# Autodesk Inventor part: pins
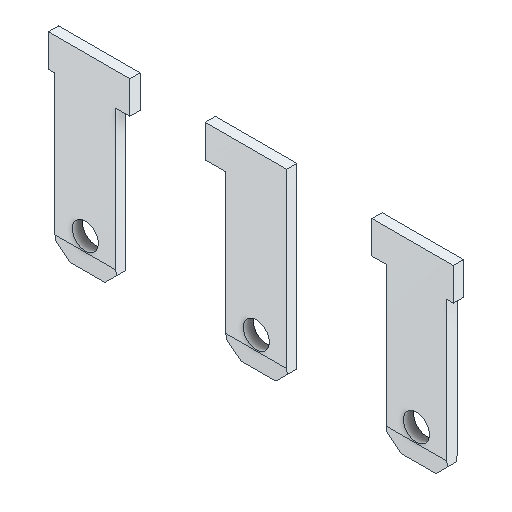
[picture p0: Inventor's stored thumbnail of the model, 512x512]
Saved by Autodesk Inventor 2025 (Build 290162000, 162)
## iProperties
Created: 2025-10
Part Number: pins
Material: Generico
Document SubType Name: Modeling
Designer: Ryzen5700u
Density: 1 g/cm^3
Appearance: Default
Author: Ryzen5700u
Revision Number: ANY
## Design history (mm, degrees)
feature "Cut-Extrude1[1]"
feature "Cut-Extrude1[2]"
feature "Cut-Extrude1[3]"
node "Solido1"
node "Solido2"
node "Solido3"
